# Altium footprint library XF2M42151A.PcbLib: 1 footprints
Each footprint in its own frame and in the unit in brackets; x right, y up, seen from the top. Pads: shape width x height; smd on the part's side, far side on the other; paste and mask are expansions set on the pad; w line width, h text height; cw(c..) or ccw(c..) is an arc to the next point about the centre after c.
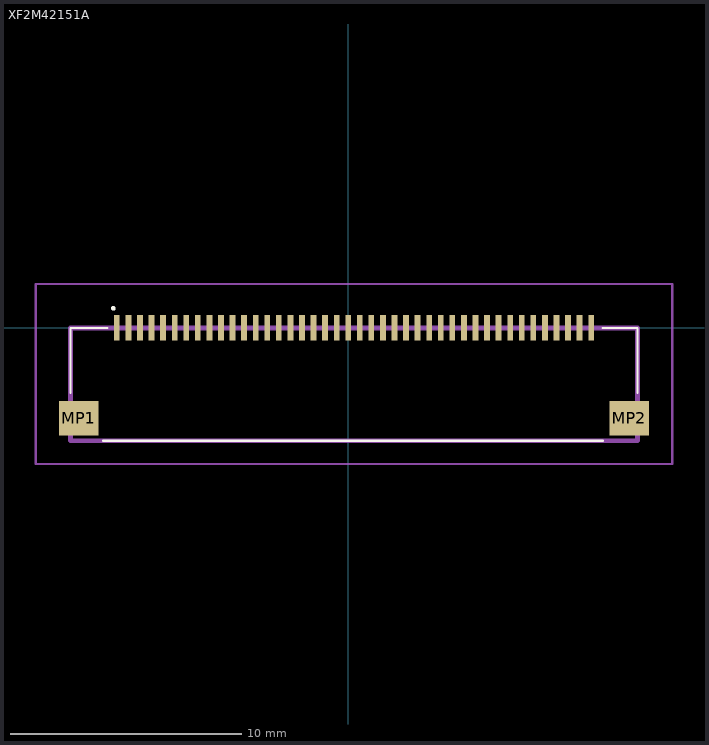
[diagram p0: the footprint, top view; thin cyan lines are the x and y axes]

## XF2M42151A [mm]
pads (44):
  rect 0.25x1.1 smd: 1(-10,0) 2(-9.5,0) 3(-9,0) 4(-8.5,0) 5(-8,0) 6(-7.5,0) 7(-7,0) 8(-6.5,0) 9(-6,0) 10(-5.5,0) 11(-5,0) 12(-4.5,0) 13(-4,0) 14(-3.5,0) 15(-3,0) 16(-2.5,0) 17(-2,0) 18(-1.5,0) 19(-1,0) 20(-0.5,0) 21(0,0) 22(0.5,0) 23(1,0) 24(1.5,0) 25(2,0) 26(2.5,0) 27(3,0) 28(3.5,0) 29(4,0) 30(4.5,0) 31(5,0) 32(5.5,0) 33(6,0) 34(6.5,0) 35(7,0) 36(7.5,0) 37(8,0) 38(8.5,0) 39(9,0) 40(9.5,0) 41(10,0) 42(10.5,0)
  rect 1.7x1.5 smd: MP1(-11.65,-3.9) MP2(12.15,-3.9)
Top Overlay:
  lines w0.1: -12,-2.8 -12,0 -10.4,0 ; -10.6,-4.88 11,-4.88 ; 11,0 12.5,0 12.5,-2.8 ; -10.2,0.85 -10.2,0.85 ; -10.2,0.85 ccw(c-10.15,0.85) -10.1,0.85 ; -10.2,0.85 cw(c-10.15,0.85) -10.1,0.85 ; -10.1,0.85 -10.1,0.85
Mechanical 15:
  lines w0.2: -12,-4.88 12.5,-4.88 12.5,0 -12,0 -12,-4.88
Mechanical 20:
  lines w0.1: -13.5,-5.88 14,-5.88 14,1.9 -13.5,1.9 -13.5,-5.88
